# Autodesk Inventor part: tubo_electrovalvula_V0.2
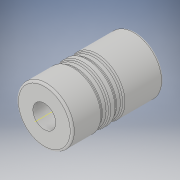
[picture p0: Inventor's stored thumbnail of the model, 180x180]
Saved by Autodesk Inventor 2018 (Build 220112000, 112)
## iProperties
Created: 2018-09
Part Number: tubo_electrovalvula_V0.2
Material: Generic
Document SubType Name: Modeling
Designer: Gordillo
Density: 1 g/cm^3
Appearance: Default
Author: Gordillo
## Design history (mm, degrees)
sketch "Sketch1"
  geometry: C1 r 55 at (0, 0); 1 further point
  constraints: 1 centre point, 1 coincident
  dimensions: "d0" = 110 diameter of C1
extrude "Extrusion1" new body sketch "Sketch1" distance "d1" = 180; taper "d2" = 0 deg
sketch "Sketch2"
  geometry: L1 (55, 180)-(-55, 180) reference; L2 (-55, 0)-(55, 0) reference; L3 (55, 0)-(55, 180) reference; L4 (55, 80)-(52, 80); L5 (52, 80)-(52, 92); L6 (52, 92)-(55, 92); L7 (55, 92)-(55, 80); L8 (55, 108)-(52, 108); L9 (52, 108)-(52, 120); L10 (52, 120)-(55, 120); L11 (55, 120)-(55, 108); L12 (0, -36)-(0, 216) reference; 1 further point
  constraints: 16 end point, 4 parallel, 2 horizontal, 2 perpendicular, 2 point on line
  dimensions: "d3" = 3 distance of L5.end L6.end; "d4" = 12 distance of L4.end L5.end; "d5" = 80 distance between parallel lines of L2 L4; "d6" = 3 distance of L9.end L10.end; "d7" = 12 distance of L8.end L9.end; "d8" = 16 distance between parallel lines of L8 L6
revolve "Revolution1" sketch "Sketch2" stored, may be unused: angle "d9" = 90 deg
fillet "Fillet1" dims "d10" = 4
sketch "Sketch3"
  geometry: C1 r 22.5 at (0, 0); 1 further point
  constraints: 1 centre point, 1 coincident
  dimensions: "d11" = 45 diameter of C1
extrude "Extrusion2" cut sketch "Sketch3" distance "d12" = 150; taper "d13" = 0 deg
fillet "Fillet2" dims "d14" = 4
workplane "Work Plane1"
sketch "Sketch4"
  geometry: L1 (0, -36)-(0, 216) reference; L2 (51, 0)-(-51, 0) reference; 2 further points
  constraints: 1 point on line
  dimensions: "d15" = 45 distance from line of L2 point (0, 45)
hole "Hole1" sketch "Sketch4" at (0, 45) diameter "d16" = 12; stored, may be unused: countersink angle "d20" = 90 deg, drill point angle "d22" = 118 deg; dims "d17" = 6, "d18" = 14, "d19" = 4, "d21" = 8
thread "Thread1" dims "d23" = 10, "d24" = 0
body "Solid1"
node "Projected Loop1"
